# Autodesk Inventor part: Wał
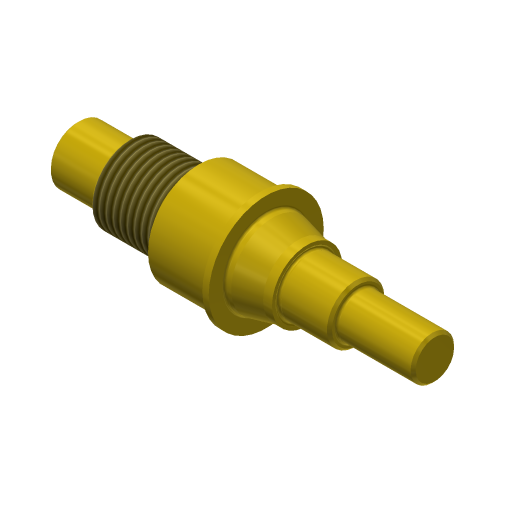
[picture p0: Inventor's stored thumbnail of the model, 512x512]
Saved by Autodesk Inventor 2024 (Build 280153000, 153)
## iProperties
Company: ATC
CustomPartVersion: 1
Created: 2023-03
Part Number: Wał
Material: Stal kuta
Document SubType Name: Modeling
Designer: Andrzej Jaskulski
Density: 1 g/cm^3
Appearance: Lśniąca — złota
Checked By: A.J.
Engr Approved By: Andrzej Jaskulski
Mfg Approved By: Andrzej Jaskulski
Authority: A.J.
Title: A.J.: Kurs R2024-MEP
Author: Andrzej Jaskulski
Revision Number: 1/24
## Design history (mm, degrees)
sketch "Szkic główny"
  geometry: L1 (0, 0)-(280, 0) reference; L2 (0, 0)-(0, 22.5); L3 (0, 22.5)-(40, 22.5); L4 (40, 22.5)-(40, 30); L5 (90, 30)-(90, 27.5); L6 (40, 30)-(90, 30); L7 (90, 27.5)-(95, 27.5); L8 (95, 27.5)-(95, 40); L9 (95, 40)-(143, 40); L10 (143, 40)-(143, 45); L11 (148, 45)-(148, 32.5); L12 (143, 45)-(148, 45); L13 (148, 32.5)-(153, 32.5); L14 (153, 32.5)-(173, 27.5); L15 (180, 27.5)-(180, 22.5); L16 (173, 27.5)-(180, 27.5); L17 (220, 22.5)-(220, 17); L18 (180, 22.5)-(220, 22.5); L19 (280, 17)-(280, 0); L20 (220, 17)-(280, 17)
  constraints: 40 end point, 11 horizontal, 9 vertical
revolve "Obrót1" sketch "Szkic główny" stored, may be unused: angle "d6" = 0 deg
chamfer "Faza12" distance "d56" = 2; stored, may be unused: second distance "d57" = 0.125, angle "d58" = 45 deg
fillet "Zaokrąglenie7" dims "d59" = 2
chamfer "Faza13" distance "d60" = 2; stored, may be unused: second distance "d61" = 0.125, angle "d62" = 45 deg
feature "Gwint3" dims "d63" = 50, "d64" = 0
chamfer "Faza14" distance "d65" = 2; stored, may be unused: second distance "d66" = 2, angle "d67" = 45 deg
fillet "Zaokrąglenie8" dims "d68" = 0.5
fillet "Zaokrąglenie9" dims "d69" = 0.5
chamfer "Faza15" distance "d70" = 0.5; stored, may be unused: second distance "d71" = 0.125, angle "d72" = 45 deg
node "Podcięcie4"
fillet "Zaokrąglenie10" dims "d73" = 2
node "Podcięcie5"
chamfer "Faza16" distance "d74" = 2; stored, may be unused: second distance "d75" = 0.125, angle "d76" = 45 deg
fillet "Zaokrąglenie11" dims "d77" = 2
chamfer "Faza17" distance "d78" = 2; stored, may be unused: second distance "d79" = 0.125, angle "d80" = 45 deg
node "Bryła1"
node "Korpusy bryłowe"
node "Korpusy powierzchniowe"
feature "iFeature1:3"
feature "iFeature1:4"
other parameters: "d0" = 0, "d1" = 0, "d2" = 0
